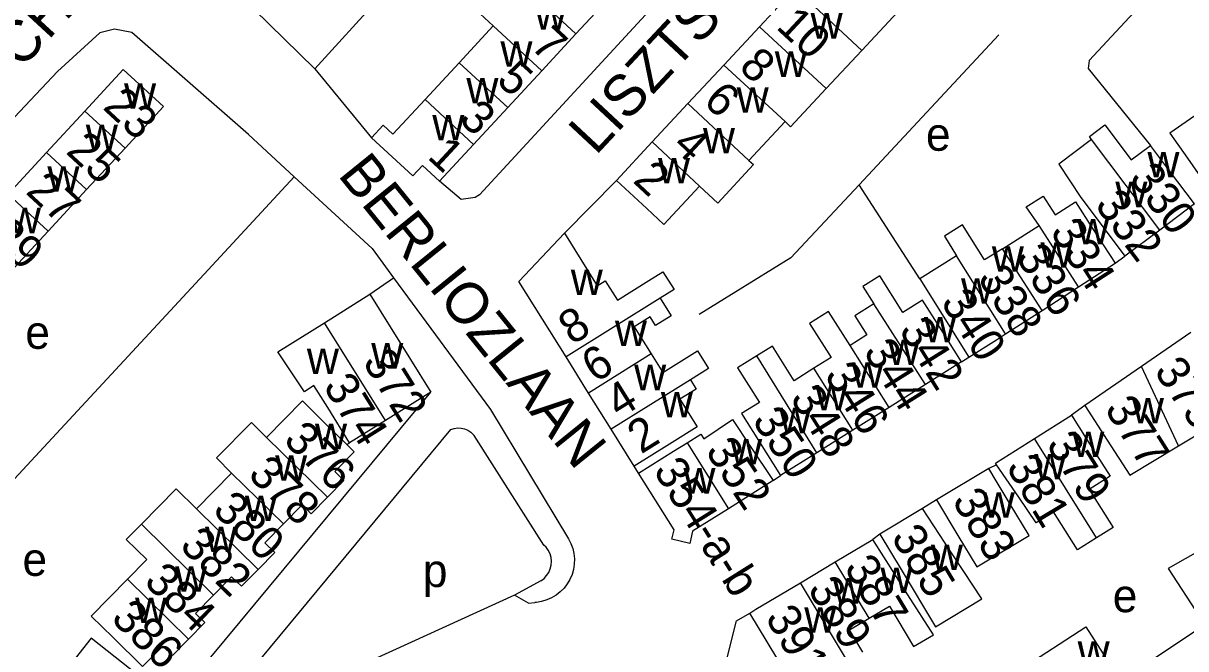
# Model space of a CAD drawing. Extents: x 159045 to 160918, y 380454 to 382516.
# Drawn here: x 159882.5 to 160022.9, y 381583.2 to 381658.8 of the extents above; entities that cross this region are included whole.
import ezdxf

# ---------------------------------------------------------------- set-up
doc = ezdxf.new("R2010")
doc.units = 0
for name, color, linetype in [('BLT_Basislijn', 7, 'Continuous'), ('BLT_Bebouwing', 7, 'Continuous'), ('BLT_Centroide', 7, 'Continuous'), ('BLT_Huisnummer', 7, 'Continuous'), ('BLT_Huisnummer_ tussenligend', 7, 'Continuous'), ('BLT_Huisnummer_reeks', 7, 'Continuous'), ('BLT_Onderverdeling_panden', 7, 'Continuous'), ('BLT_Straatnaam', 7, 'Continuous')]:
    doc.layers.add(name, color=color, linetype=linetype)

msp = doc.modelspace()

# ---------------------------------------------------------------- linework, layer by layer
at = {"layer": 'BLT_Basislijn'}
for p, q in [((159969.93, 381710.61), (159917.66, 381653.32)), ((159917.66, 381653.32), (159910.3, 381660.51)), ((159983.42, 381639.27), (160000.3, 381657.4)), ((159917.66, 381653.32), (159924.53, 381644.98)), ((159915.2, 381640.27), (159904.79, 381629.03)), ((159990.74, 381627.91), (159983.42, 381639.27)), ((160014.32, 381629.82), (160015.51, 381630.67)), ((159904.79, 381629.03), (159861.07, 381581.84)), ((159924.3, 381626.09), (159927.18, 381628.07)), ((159995.78, 381617.88), (159996.67, 381618.47)), ((159879.08, 381550.82), (159931.69, 381614.23)), ((160010.65, 381612.61), (160009.05, 381611.47)), ((159909.99, 381580.6), (159934.12, 381609.7)), ((159945.35, 381595.75), (159936.9, 381608.98)), ((159921.87, 381608.11), (159921.6, 381607.85)), ((160000, 381605.43), (159999.08, 381604.99)), ((159956.76, 381604.44), (159956.25, 381605.29)), ((159973.04, 381603.55), (159973.92, 381604.16)), ((159992.76, 381601.2), (159991.08, 381600.17)), ((159985.93, 381597.08), (159985.05, 381596.44)), ((159944.98, 381591.44), (159941.77, 381589.71)), ((159943.47, 381588.75), (159941.77, 381589.71)), ((159943.47, 381588.75), (159944.26, 381588.81))]:
    msp.add_line(p, q, dxfattribs=at)
for points in [[(159980.68, 381697.17), (159983.27, 381694.65), (159984.45, 381693.04), (159984.62, 381692.27), (159984.54, 381689.65), (159983.35, 381687.78), (159937.56, 381638.1), (159937.02, 381637.74), (159935.33, 381637.53), (159932.73, 381639.72)], [(160025.39, 381667.13), (160021.42, 381663.29), (160019.84, 381663.66), (160011.18, 381654.32), (160011.08, 381653.33), (160018.61, 381644.05)], [(159909.68, 381645.37), (159895.56, 381657.72), (159893.47, 381658.11), (159891.72, 381657.68), (159886.61, 381653), (159839.03, 381602.45)], [(159909.68, 381645.37), (159915.2, 381640.27)], [(159915.2, 381640.27), (159924.58, 381631.59), (159927.18, 381628.07)], [(159954.1, 381639.83), (159947.81, 381633.45)], [(159983.42, 381639.27), (159975.18, 381630.45), (159964.08, 381623.6)], [(159927.18, 381628.07), (159938.91, 381612.13), (159948.32, 381596.51)], [(159934.12, 381609.7), (159934.52, 381609.84), (159934.94, 381609.91), (159935.36, 381609.9), (159935.77, 381609.81), (159936.15, 381609.64), (159936.5, 381609.4), (159936.8, 381609.11), (159936.9, 381608.98)], [(159948.32, 381596.51), (159948.61, 381595.95), (159948.83, 381595.34), (159948.97, 381594.72), (159949.03, 381594.08), (159949.01, 381593.45), (159948.91, 381592.81), (159948.74, 381592.2), (159948.48, 381591.61), (159948.16, 381591.06), (159947.77, 381590.55), (159947.32, 381590.1), (159946.82, 381589.7), (159946.27, 381589.38), (159945.69, 381589.12), (159945.07, 381588.93), (159944.44, 381588.83), (159944.26, 381588.81)], [(159944.98, 381591.44), (159945.36, 381591.72), (159945.67, 381592.06), (159945.93, 381592.45), (159946.11, 381592.87), (159946.22, 381593.33), (159946.25, 381593.79), (159946.2, 381594.25), (159946.08, 381594.7), (159945.87, 381595.12), (159945.6, 381595.5), (159945.35, 381595.75)], [(159941.77, 381589.71), (159924.75, 381581.94), (159923.64, 381580.95), (159914.75, 381574.14)], [(160014.97, 381579.35), (160025.04, 381586.09), (160028.83, 381579.95)]]:
    msp.add_lwpolyline(points, dxfattribs=at)
at = {"layer": 'BLT_Bebouwing'}
for p, q in [((159975.7, 381663.03), (159971.38, 381658.39)), ((159988.05, 381660.17), (159983.73, 381655.53)), ((159935.11, 381654.05), (159939.22, 381658.51)), ((159949.21, 381657.53), (159945.09, 381653.08)), ((159971.38, 381658.39), (159967.06, 381653.75)), ((159983.73, 381655.53), (159979.43, 381650.92)), ((159930.99, 381649.6), (159935.11, 381654.05)), ((159967.06, 381653.75), (159962.74, 381649.11)), ((159945.09, 381653.08), (159940.97, 381648.63)), ((159962.74, 381649.11), (159958.42, 381644.47)), ((159885.27, 381643.2), (159889.91, 381648.21)), ((159940.97, 381648.63), (159936.85, 381644.18)), ((159894.75, 381643.73), (159890.12, 381638.72)), ((159936.85, 381644.18), (159932.73, 381639.72)), ((159958.42, 381644.47), (159954.1, 381639.83)), ((159880.63, 381638.18), (159885.27, 381643.2)), ((159890.12, 381638.72), (159885.48, 381633.7)), ((160023.92, 381636.98), (160019.71, 381633.82)), ((159885.48, 381633.7), (159880.84, 381628.69)), ((160000.73, 381631.56), (160005.14, 381634.39)), ((160019.71, 381633.82), (160015.51, 381630.67)), ((159995.18, 381630.7), (159990.74, 381627.91)), ((160009.91, 381626.97), (160014.32, 381629.82)), ((159990.74, 381627.91), (159996.67, 381618.47)), ((160005.51, 381624.12), (160009.91, 381626.97)), ((159918.84, 381622.63), (159924.3, 381626.09)), ((159924.3, 381626.09), (159931.69, 381614.23)), ((160001.1, 381621.28), (160005.51, 381624.12)), ((160023.46, 381621.45), (160017.51, 381617.34)), ((159950.73, 381614.13), (159948.02, 381618.49)), ((159995.78, 381617.88), (159991.41, 381615.14)), ((160017.51, 381617.34), (160010.65, 381612.61)), ((159931.69, 381614.23), (159926.2, 381610.81)), ((159953.45, 381609.77), (159950.73, 381614.13)), ((159991.41, 381615.14), (159987.04, 381612.39)), ((159987.04, 381612.39), (159982.67, 381609.65)), ((160004.59, 381608.65), (160009.05, 381611.47)), ((159926.2, 381610.81), (159921.87, 381608.11)), ((159956.25, 381605.29), (159953.45, 381609.77)), ((159982.67, 381609.65), (159978.29, 381606.9)), ((159978.29, 381606.9), (159973.92, 381604.16)), ((159907.63, 381604.46), (159903.38, 381600.13)), ((159999.08, 381604.99), (159992.76, 381601.2)), ((159973.04, 381603.55), (159967.62, 381600.15)), ((159991.08, 381600.17), (159985.93, 381597.08)), ((159980.53, 381593.73), (159985.05, 381596.44)), ((159976.31, 381591.2), (159980.53, 381593.73)), ((159970.95, 381587.99), (159976.31, 381591.2)), ((159970.21, 381587.54), (159970.95, 381587.99))]:
    msp.add_line(p, q, dxfattribs=at)
for points in [[(159943.34, 381662.96), (159947.46, 381667.41), (159949.65, 381665.38), (159953.32, 381661.98), (159949.21, 381657.53)], [(159939.22, 381658.51), (159936.58, 381660.91), (159940.62, 381665.28), (159943.34, 381662.96)], [(159889.91, 381648.21), (159894.54, 381653.22), (159899.39, 381648.74), (159894.75, 381643.73)], [(159979.43, 381650.92), (159975.14, 381646.3), (159974.46, 381646.93)], [(159924.53, 381644.98), (159925.93, 381646.49), (159927.1, 381645.4), (159930.99, 381649.6)], [(160025.91, 381649.01), (160020.94, 381645.55), (160023.07, 381642.5), (160025.93, 381638.39)], [(159974.46, 381646.93), (159970.11, 381642.25)], [(160011.49, 381644.77), (160011.22, 381645.14), (160013.09, 381646.54), (160016.28, 381642.3), (160018.61, 381644.05)], [(159932.73, 381639.72), (159930.67, 381641.62), (159929.51, 381640.37), (159924.53, 381644.98)], [(160011.49, 381644.77), (160007.52, 381641.79), (160010.19, 381637.76), (160012.51, 381634.67), (160015.51, 381630.67)], [(160023.92, 381636.98), (160020.91, 381640.98), (160018.61, 381644.05)], [(159970.11, 381642.25), (159970.67, 381641.73), (159966.35, 381637.09), (159964.15, 381639.13)], [(159954.1, 381639.83), (159957.76, 381636.42), (159959.83, 381634.49), (159964.15, 381639.13)], [(160005.14, 381634.39), (160003.6, 381636.64), (160005.62, 381637.92), (160007.08, 381635.65), (160009.55, 381637.22), (160011.61, 381634.02), (160014.32, 381629.82)], [(160000.73, 381631.56), (159998.55, 381630.22), (159995.89, 381634.45), (159993.71, 381633.08), (159995.18, 381630.7)], [(159948.02, 381618.49), (159942.33, 381627.6), (159947.81, 381633.45)], [(159947.81, 381633.45), (159951.79, 381627.08), (159952.75, 381627.69), (159954.22, 381625.34), (159958.03, 381627.72), (159959.72, 381628.77), (159961.06, 381626.63), (159959.37, 381625.58)], [(159995.78, 381617.88), (159993.12, 381622.12), (159991.08, 381625.37), (159988.69, 381623.87), (159985.92, 381628.29), (159983.86, 381626.99), (159985.18, 381624.89)], [(159959.37, 381625.58), (159960.71, 381623.44), (159958.83, 381622.27), (159958.18, 381623.32), (159956.25, 381622.11), (159958.29, 381618.85)], [(159982.34, 381619.88), (159979.71, 381623.99), (159977.42, 381622.55), (159980.02, 381618.42), (159977.96, 381617.13)], [(159985.18, 381624.89), (159982.9, 381623.46), (159984.36, 381621.15), (159982.34, 381619.88)], [(159917.56, 381615.04), (159916.42, 381614.28), (159913.2, 381619.11), (159918.84, 381622.63)], [(159996.67, 381618.47), (160000.01, 381620.57), (160001.1, 381621.28)], [(159977.96, 381617.13), (159975.56, 381615.62), (159972.94, 381619.8), (159971.04, 381618.61)], [(159958.29, 381618.85), (159959.71, 381616.59), (159963.91, 381619.21), (159965.22, 381617.11), (159963.03, 381615.74)], [(159971.04, 381618.61), (159968.73, 381617.16), (159971.36, 381612.98), (159969.22, 381611.64), (159971.26, 381608.39), (159973.92, 381604.16)], [(159963.03, 381615.74), (159963.74, 381614.6), (159961.77, 381613.37), (159963.85, 381610.03), (159960.49, 381607.94), (159956.25, 381605.29)], [(159921.87, 381608.11), (159919.23, 381612.36), (159917.56, 381615.04)], [(159921.6, 381607.85), (159918.86, 381610.54), (159916.18, 381613.17), (159911.85, 381608.76)], [(160010.65, 381612.61), (160013.37, 381608.42), (160016.1, 381604.21), (160021.97, 381607.73)], [(160009.05, 381611.47), (160011.72, 381607.24), (160013.71, 381604.08), (160011.18, 381602.48), (160014.08, 381597.89), (160012.09, 381596.64)], [(159911.85, 381608.76), (159910.02, 381610.58), (159905.8, 381606.29), (159907.63, 381604.46)], [(159962.65, 381608.12), (159964.3, 381609.15), (159964.64, 381608.61), (159968.13, 381610.93), (159970.27, 381607.71), (159973.04, 381603.55)], [(160021.97, 381607.73), (160027.01, 381610.75), (160028.8, 381607.77), (160031.12, 381609.17)], [(160000, 381605.43), (159999.86, 381605.66), (160000, 381605.75), (160004.59, 381608.65)], [(159921.6, 381607.85), (159922.43, 381607.04), (159920.08, 381604.64), (159921.18, 381603.56), (159919.2, 381601.55)], [(159956.76, 381604.44), (159961, 381607.09), (159962.65, 381608.12)], [(160012.09, 381596.64), (160009.8, 381595.19), (160006.9, 381599.78), (160004.79, 381598.45), (160002.68, 381601.53), (160000, 381605.43)], [(159960.8, 381596.45), (159961.06, 381597.59), (159956.76, 381604.44)], [(159992.76, 381601.2), (159995.33, 381596.91), (159997.61, 381593.12), (160003.93, 381596.91), (160001.65, 381600.7), (159999.98, 381603.5), (159999.08, 381604.99)], [(159903.38, 381600.13), (159900.94, 381602.55), (159896.73, 381598.28)], [(159919.2, 381601.55), (159917.22, 381599.53), (159916.14, 381600.6), (159913.9, 381598.32)], [(159967.62, 381600.15), (159963.3, 381597.43), (159962.96, 381595.96), (159960.8, 381596.45)], [(159985.93, 381597.08), (159988.5, 381592.79), (159992.64, 381585.88), (159998.24, 381589.24), (159993.82, 381595.99), (159991.08, 381600.17)], [(159896.73, 381598.28), (159894.91, 381596.43), (159897.37, 381594.01), (159895.05, 381591.65)], [(159913.9, 381598.32), (159911.65, 381596.03), (159912.84, 381594.87), (159910.82, 381592.82)], [(160026, 381597.41), (160026.63, 381596.28), (160020.74, 381592.91), (160024.56, 381587.02), (160029.82, 381590.55), (160032.58, 381585.6)], [(159984.62, 381586.92), (159987.06, 381588.38), (159989.99, 381583.49), (159992.38, 381584.92), (159989.31, 381589.74), (159987.73, 381592.22), (159985.05, 381596.44)], [(159910.82, 381592.82), (159908.8, 381590.77), (159907.63, 381591.92), (159905.45, 381589.7)], [(159895.05, 381591.65), (159890.66, 381587.17), (159893.31, 381584.57), (159896.87, 381581.07)], [(159905.45, 381589.7), (159903.27, 381587.48), (159904.38, 381586.39), (159902.43, 381584.4)], [(159971.92, 381570.39), (159966.72, 381579.05), (159968.61, 381586.58), (159970.21, 381587.54)], [(159983.84, 381582.81), (159982.23, 381585.49), (159984.62, 381586.92)], [(160004.77, 381577.79), (160002.87, 381580.71), (160010.77, 381585.88), (160014.97, 381579.35)], [(159896.07, 381580.24), (159893.58, 381582.21), (159890.68, 381584.51), (159886.8, 381579.6)], [(159902.43, 381584.4), (159900.47, 381582.41), (159899.31, 381583.55), (159896.87, 381581.07)]]:
    msp.add_lwpolyline(points, dxfattribs=at)
at = {"layer": 'BLT_Onderverdeling_panden'}
for p, q in [((159983.73, 381655.53), (159975.7, 381663.03)), ((159949.21, 381657.53), (159943.34, 381662.96)), ((159945.09, 381653.08), (159939.22, 381658.51)), ((159979.43, 381650.92), (159971.38, 381658.39)), ((159940.97, 381648.63), (159935.11, 381654.05)), ((159974.46, 381646.93), (159967.06, 381653.75)), ((159936.85, 381644.18), (159930.99, 381649.6)), ((159970.11, 381642.25), (159962.74, 381649.11)), ((159894.75, 381643.73), (159889.91, 381648.21)), ((160019.71, 381633.82), (160011.49, 381644.77)), ((159964.15, 381639.13), (159958.42, 381644.47)), ((159890.12, 381638.72), (159885.27, 381643.2)), ((159885.48, 381633.7), (159880.63, 381638.18)), ((160009.91, 381626.97), (160005.14, 381634.39)), ((160001.1, 381621.28), (159995.18, 381630.7)), ((160005.51, 381624.12), (160000.73, 381631.56)), ((159959.37, 381625.58), (159948.02, 381618.49)), ((159991.41, 381615.14), (159985.18, 381624.89)), ((159987.04, 381612.39), (159982.34, 381619.88)), ((159958.29, 381618.85), (159950.73, 381614.13)), ((159978.29, 381606.9), (159971.04, 381618.61)), ((159982.67, 381609.65), (159977.96, 381617.13)), ((160021.97, 381607.73), (160017.51, 381617.34)), ((159963.03, 381615.74), (159953.45, 381609.77)), ((159919.2, 381601.55), (159911.85, 381608.76)), ((160012.09, 381596.64), (160004.59, 381608.65)), ((159962.65, 381608.12), (159967.62, 381600.15)), ((159913.9, 381598.32), (159907.63, 381604.46)), ((159910.82, 381592.82), (159903.38, 381600.13)), ((159905.45, 381589.7), (159896.73, 381598.28)), ((159984.62, 381586.92), (159980.53, 381593.73)), ((159902.43, 381584.4), (159895.05, 381591.65)), ((159982, 381581.71), (159976.31, 381591.2)), ((159974.52, 381580.39), (159970.21, 381587.54))]:
    msp.add_line(p, q, dxfattribs=at)
msp.add_lwpolyline([(159926.2, 381610.81), (159918.84, 381622.63)], dxfattribs=at)

# ---------------------------------------------------------------- texts
at = {"layer": 'BLT_Centroide'}
for s, p in [('w', (159944.22, 381658.03)), ('w', (159977.55, 381656.97)), ('w', (159940.09, 381653.56)), ('w', (159973.23, 381652.34)), ('w', (159935.98, 381649.12)), ('w', (159894.64, 381648.48)), ('w', (159968.62, 381648)), ('w', (159931.86, 381644.66)), ('w', (159890.02, 381643.47)), ('w', (159964.55, 381643.09)), ('e', (159991.48, 381643.41)), ('w', (159959.12, 381639.47)), ('w', (160018.23, 381640.19)), ('w', (159885.38, 381638.45)), ('w', (160014.36, 381636.59)), ('w', (159880.73, 381633.44)), ('w', (160009.73, 381632.09)), ('w', (160005.31, 381629.27)), ('w', (159999.44, 381628.78)), ('w', (159948.59, 381625.97)), ('w', (159995.72, 381624.92)), ('e', (159882.71, 381619.47)), ('w', (159953.92, 381619.81)), ('w', (159991.25, 381620.25)), ('w', (159916.72, 381616.41)), ('w', (159924.49, 381617.09)), ('w', (159986.88, 381617.52)), ('w', (159956.24, 381614.47)), ('w', (159982.5, 381614.77)), ('w', (159959.47, 381611.19)), ('w', (159978.12, 381612.02)), ('w', (160016.36, 381610.47)), ('w', (159973.75, 381609.27)), ('w', (159917.7, 381607.34)), ('w', (159967.84, 381605.52)), ('w', (160009.16, 381606.38)), ('w', (159912.88, 381603.53)), ('w', (160004.55, 381603.7)), ('w', (159962.19, 381601.98)), ('w', (159909.23, 381598.66)), ('w', (159998.34, 381599.05)), ('w', (159904.41, 381594.91)), ('w', (159992.08, 381592.72)), ('e', (159882.37, 381592.03)), ('w', (159900.8, 381590.12)), ('p', (159930.72, 381590.68)), ('w', (159985.98, 381589.97)), ('w', (159980.22, 381588.69)), ('e', (160014.04, 381587.64)), ('w', (159895.96, 381586.34)), ('w', (159976.78, 381585.17)), ('w', (160009.8, 381581.04))]:
    msp.add_text(s, height=4, dxfattribs=at).set_placement(p)
at = {"layer": 'BLT_Huisnummer'}
for s, rotation, p in [('10', 317.048, (159973.25, 381658.27)), ('5', 317.2172, (159939.46, 381651.75)), ('23', 317.242, (159891.94, 381648.55)), ('6', 317.048, (159964.44, 381649.21)), ('1', 317.2225, (159931.14, 381642.57)), ('2', 317.0425, (159955.97, 381639.68)), ('330', 306.8859, (160015.91, 381640.06)), ('27', 317.2411, (159882.63, 381638.33)), ('334', 302.7321, (160006.39, 381633.62)), ('338', 302.7341, (159997.63, 381628.01)), ('8', 31.9886, (159948.74, 381619.87)), ('342', 302.1325, (159988.14, 381621.71)), ('372', 301.9581, (159923.37, 381617.88)), ('346', 302.1325, (159979.13, 381616.28)), ('377', 302.2794, (160012.97, 381612.22)), ('350', 303.6138, (159970.41, 381610.8)), ('2', 31.9738, (159957.07, 381606.69)), ('376', 315.5233, (159913.75, 381608.27)), ('381', 300.9678, (160001.09, 381605.2)), ('380', 315.5205, (159905.19, 381599.82)), ('385', 300.9588, (159987.21, 381596.72)), ('384', 315.521, (159896.9, 381591.18)), ('389', 301.0793, (159977.12, 381590.44))]:
    msp.add_text(s, height=4, rotation=rotation, dxfattribs=at).set_placement(p)
at = {"layer": 'BLT_Huisnummer_ tussenligend'}
for s, rotation, p in [('7', 317.2172, (159943.59, 381655.9)), ('8', 317.048, (159968.74, 381653.35)), ('3', 317.2225, (159934.95, 381647.02)), ('25', 317.242, (159887.49, 381643.18)), ('4', 317.0425, (159960.71, 381643.84)), ('332', 306.8859, (160011.77, 381636.83)), ('29', 317.2411, (159878.19, 381632.8)), ('336', 302.7321, (160002.25, 381630.55)), ('340', 302.7341, (159993.18, 381625.1)), ('6', 31.9738, (159951.54, 381615.28)), ('344', 302.1325, (159983.84, 381619.12)), ('375', 304.6202, (160018.94, 381616.75)), ('374', 301.9581, (159918.61, 381614.93)), ('4', 31.9738, (159954.45, 381610.98)), ('348', 302.1325, (159974.99, 381613.51)), ('352', 303.6138, (159964.75, 381607.11)), ('379', 302.2794, (160005.92, 381607.92)), ('378', 315.5233, (159909.46, 381604.12)), ('383', 300.9678, (159994.56, 381601.13)), ('382', 315.5205, (159901.21, 381595.51)), ('387', 300.9588, (159981.53, 381593.05)), ('386', 315.521, (159892.92, 381586.73)), ('391', 301.0793, (159971.99, 381586.98))]:
    msp.add_text(s, height=4, rotation=rotation, dxfattribs=at).set_placement(p)
at = {"layer": 'BLT_Huisnummer_reeks'}
msp.add_text('354-a-b', height=4, rotation=302.124, dxfattribs=at).set_placement((159958.48, 381604.76))
at = {"layer": 'BLT_Straatnaam'}
for s, height, rotation, p in [('SCHUMANNSTRAAT', 5, 47.2729, (159879.18, 381649.88)), ('LISZTSTRAAT', 5, 46.979, (159951.6, 381642.75)), ('BERLIOZLAAN', 4.9999, 308.9584, (159920.35, 381640.47)), ('DE FALLASTRAAT', 5, 316.7776, (159837.99, 381580.25))]:
    msp.add_text(s, height=height, rotation=rotation, dxfattribs=at).set_placement(p)

doc.saveas('drawing.dxf')
